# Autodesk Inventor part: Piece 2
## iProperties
Created: 2006-10
Part Number: Piece 2
Document SubType Name: Modeling
Designer: Lab User
Author: Lab User
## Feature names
1. Extrusion1
2. Hole1
3. Hole9
4. Hole10
5. Hole11
6. Hole12
